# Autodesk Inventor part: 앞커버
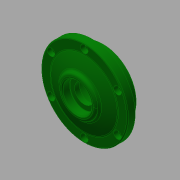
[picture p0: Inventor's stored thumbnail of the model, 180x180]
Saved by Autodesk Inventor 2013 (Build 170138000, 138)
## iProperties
Created: 2016-05
Part Number: 앞커버
Document SubType Name: Modeling
Designer: mduedu
Density: 2.71 g/cm^3
Material: 알루미늄 6061
Author: mduedu
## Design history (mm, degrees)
sketch "스케치1"
  geometry: C1 r 35 at (0, 0); C2 r 45 at (0, 0); 1 further point
  constraints: 2 centre point, 2 coincident
  dimensions: "d33" = 90 diameter of C2; "d34" = 70 diameter of C1
extrude "돌출1" new body sketch "스케치1" distance "d0" = 8; taper "d1" = 0 deg
extrude "돌출2" join sketch "스케치1" distance "d2" = 8; taper "d3" = 0 deg; dims "d35" = 12, "d36" = 0
sketch "스케치5"
  geometry: L1 (-45, 8)-(45, 8) reference; L2 (0, 0)-(0, 15); L3 (-45, 0)-(45, 0) reference; L4 (35, 8)-(0, 8); A1 r 91 centre (0, -76) between (35, 8) and (0, 15)
  constraints: 4 end point, 3 point on line, 2 point on circle, 1 centre point, 1 midpoint, 1 perpendicular
  dimensions: "d37" = 35 distance from line of L2 L4.start; "d39" = 7 distance from line of L1 L2.end
revolve "회전2" sketch "스케치5" stored, may be unused: angle "d40" = 90 deg
node "작업 평면1"
sketch "스케치6"
  geometry: C1 r 20 at (0, 0); 1 further point
  constraints: 1 centre point, 1 coincident
  dimensions: "d42" = 40 diameter of C1
extrude "돌출4" join sketch "스케치6" stored distance "d43" = 10; taper "d44" = 0 deg
sketch "스케치4"
  geometry: L1 (0, -12)-(0, 16); L2 (-20, -12)-(-20, 0); L3 (-20, 0)-(-15, 0); L4 (-15, 0)-(-15, 3); L5 (-15, 3)-(-10, 3); L6 (-10, 3)-(-10, 8); L7 (-10, 8)-(-15, 8); L8 (-15, 8)-(-15, 16); L9 (35, -12)-(-35, -12) reference; L10 (-20, 16)-(20, 16) reference; 1 further point
  constraints: 16 end point, 6 parallel, 3 point on line, 2 midpoint, 1 perpendicular, 1 vertical
  dimensions: "d15" = 40 diameter of L2 L1; "d16" = 30 diameter of L8 L1; "d18" = 12 distance of L2.start L2.end; "d19" = 3 distance of L3.end L4.end; "d20" = 30 diameter of L4 L1; "d21" = 20 diameter of L6 L1; "d45" = 8 distance of L7.end L8.end
revolve "회전1" sketch "스케치4" stored, may be unused: angle "d22" = 90 deg
fillet "모깎기2" dims "d23" = 3
fillet "모깎기3" dims "d24" = 0.3
chamfer "모따기2" distance "d46" = 1; stored, may be unused: second distance "d47" = 2, angle "d48" = 45 deg
fillet "모깎기4" dims "d49" = 3
fillet "모깎기5" dims "d50" = 3
fillet "모깎기6" dims "d51" = 1
sketch "스케치7" dims "d52" = 80
  geometry: C1 r 35.595 at (0, 0) reference; C2 r 44 at (0, 0) reference; 7 further points
  constraints: 2 vertical alignment, 1 coincident, 9 other
  dimensions: "d55" = 360 deg dimension on C1.centre point (0, 40) (derived)
sketch "스케치8"
  geometry: 6 further points
  constraints: 6 other
hole "구멍2" sketch "스케치8" at (-34.641, 20), (-34.641, -20), (0, -40), (34.641, -20), (34.641, 20), (0, 40) diameter "d57" = 4.5; stored, may be unused: countersink angle "d61" = 90 deg, drill point angle "d63" = 0 deg; dims "d58" = 6, "d59" = 8, "d60" = 4.6, "d62" = 8
node "솔리드1"
other parameters: "d41" = 8
